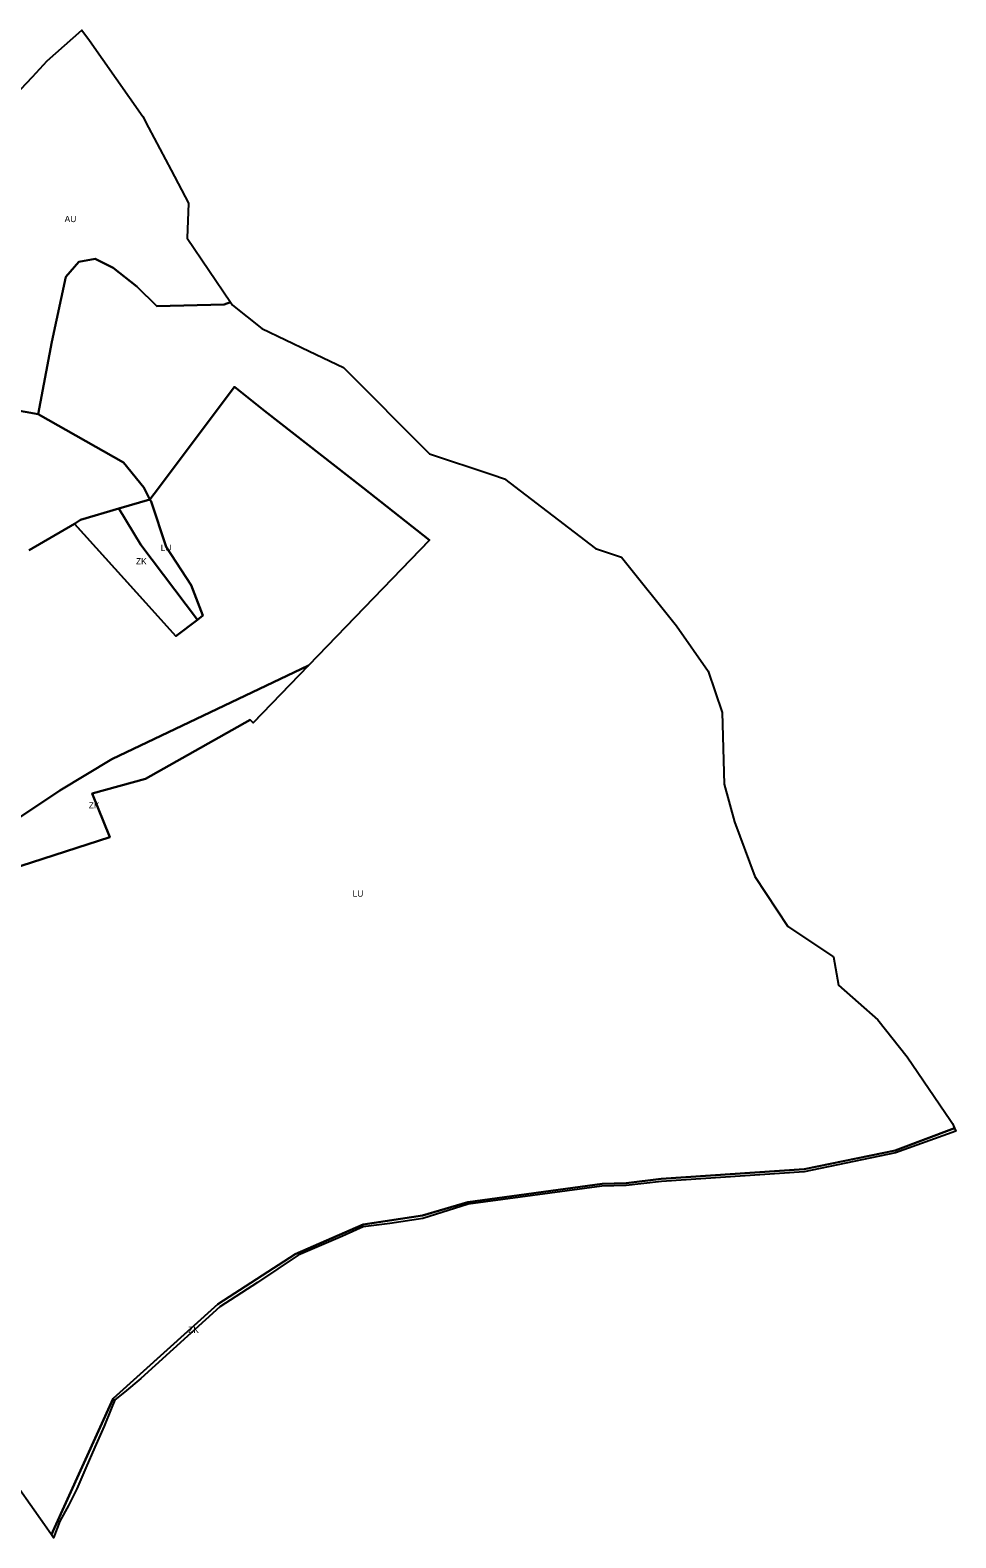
# Model space of a CAD drawing. Extents: x -521261 to -517465, y -1182764 to -1179456.
# Drawn here: x -518203 to -517465, y -1182764 to -1181562 of the extents above; entities that cross this region are included whole.
import ezdxf

# ---------------------------------------------------------------- set-up
doc = ezdxf.new("R2010")
doc.units = 0
for name, color, linetype in [('90710013', 7, 'Continuous'), ('90730013', 7, 'Continuous'), ('90750013', 7, 'Continuous'), ('90770013', 7, 'Continuous')]:
    doc.layers.add(name, color=color, linetype=linetype)

msp = doc.modelspace()

# ---------------------------------------------------------------- linework, layer by layer
at = {"layer": '90710013'}
for points in [[(-518132.326, -1181942.9), (-518114.8, -1181971.88), (-518069.54, -1182031.68), (-518086.87, -1182044.67), (-518110.82, -1182018.11), (-518167.73, -1181955), (-518162.77, -1181951.82)], [(-518263.83, -1182245.02), (-518331.496, -1182282.593), (-518305.68, -1182252.07), (-518179.3, -1182167.62), (-518137.82, -1182142.72), (-517980.99, -1182067.93), (-518025.29, -1182113.9), (-518027.56, -1182111.28), (-518111.08, -1182158.35), (-518153.43, -1182170.1), (-518139.38, -1182204.87)], [(-518186, -1182761.1), (-518185.03, -1182758.6), (-518136.91, -1182652.41), (-518053.48, -1182577.3), (-517991.81, -1182537.48), (-517937.38, -1182513.75), (-517890.3, -1182506.61), (-517854.15, -1182495.98), (-517747.01, -1182481.25), (-517727.83, -1182480.7), (-517699.99, -1182477.2), (-517585.78, -1182469.65), (-517513.36, -1182454.7), (-517465.93, -1182436.99), (-517464.94, -1182439.27), (-517512.98, -1182456.69), (-517585.76, -1182471.75), (-517699.75, -1182479.52), (-517727.75, -1182482.61), (-517747.25, -1182483.11), (-517853.64, -1182497.6), (-517889.93, -1182508.92), (-517916.3, -1182512.99), (-517937.58, -1182515.7), (-517954.01, -1182523.06), (-517989.22, -1182538.07), (-518021.76, -1182560.09), (-518051.88, -1182579.31), (-518114.7, -1182636.54), (-518127.82, -1182647.32), (-518135.52, -1182653.62), (-518138.53, -1182660.75), (-518143.89, -1182674.62), (-518151.47, -1182691.27), (-518158.69, -1182707.68), (-518165.82, -1182724.54), (-518172.44, -1182737.72), (-518179.44, -1182750.16), (-518184.3, -1182763.53)]]:
    msp.add_lwpolyline(points, close=True, dxfattribs=at)
at = {"layer": '90730013'}
msp.add_lwpolyline([(-518217.29, -1181863.99), (-518196.73, -1181867.61), (-518128.46, -1181906.25), (-518112.47, -1181926.13), (-518107.48, -1181935.62), (-518132.326, -1181942.9), (-518162.77, -1181951.82), (-518167.73, -1181955), (-518203.86, -1181976.19)], dxfattribs=at)
at = {"layer": '90750013'}
for points in [[(-518210.43, -1181608.65), (-518201.08, -1181598.66), (-518198.24, -1181595.51), (-518189.41, -1181586), (-518161.68, -1181561.54), (-518155.8, -1181569.88), (-518113.09, -1181630.49), (-518108.52, -1181639.23), (-518090.66, -1181673.2), (-518076.8, -1181699.59), (-518077.8, -1181727.26), (-518043.21, -1181778.53), (-518048.19, -1181780.36), (-518102.12, -1181781.59), (-518117.96, -1181765.95), (-518136.81, -1181751.12), (-518151.04, -1181743.73), (-518164.27, -1181746.2), (-518174.5, -1181758.25), (-518185.6, -1181810.01), (-518196.73, -1181867.61), (-518217.29, -1181863.99)], [(-518203.86, -1181976.19), (-518167.73, -1181955), (-518110.82, -1182018.11), (-518086.87, -1182044.67), (-518069.54, -1182031.68), (-518065.44, -1182028.22), (-518074.66, -1182003.92), (-518094.59, -1181973.57), (-518106.56, -1181937.37), (-518107.48, -1181935.62), (-518104.15, -1181931.16), (-518039.97, -1181846.02), (-518016.25, -1181865.06), (-517937.47, -1181926.51), (-517884.7, -1181968.01), (-517980.99, -1182067.93), (-518137.82, -1182142.72), (-518179.3, -1182167.62), (-518305.68, -1182252.07)]]:
    msp.add_lwpolyline(points, dxfattribs=at)
at = {"layer": '90770013'}
msp.add_lwpolyline([(-518263.83, -1182245.02), (-518139.38, -1182204.87), (-518153.43, -1182170.1), (-518111.08, -1182158.35), (-518027.56, -1182111.28), (-518025.29, -1182113.9), (-517884.7, -1181968.01), (-517937.47, -1181926.51), (-518016.25, -1181865.06), (-518039.97, -1181846.02), (-518104.15, -1181931.16), (-518107.48, -1181935.62), (-518112.47, -1181926.13), (-518128.46, -1181906.25), (-518196.73, -1181867.61), (-518185.6, -1181810.01), (-518174.5, -1181758.25), (-518164.27, -1181746.2), (-518151.04, -1181743.73), (-518136.81, -1181751.12), (-518117.96, -1181765.95), (-518102.12, -1181781.59), (-518048.19, -1181780.36), (-518043.21, -1181778.53), (-518041.71, -1181780.74), (-518018.25, -1181799.32), (-517980.44, -1181817.45), (-517953.14, -1181830.53), (-517884.53, -1181899.44), (-517834.98, -1181915.87), (-517824.86, -1181919.18), (-517752.33, -1181974.82), (-517731.51, -1181981.82), (-517687.7, -1182036.43), (-517662.52, -1182072.49), (-517651.3, -1182105.53), (-517649.72, -1182162.65), (-517641.34, -1182192.65), (-517625.29, -1182236.25), (-517598.88, -1182276.27), (-517562.58, -1182300.26), (-517558.45, -1182323.01), (-517527.07, -1182350.65), (-517503.79, -1182380.06), (-517469.24, -1182430.75), (-517467.55, -1182433.23), (-517465.93, -1182436.99), (-517513.36, -1182454.7), (-517585.78, -1182469.65), (-517699.99, -1182477.2), (-517727.83, -1182480.7), (-517747.01, -1182481.25), (-517854.15, -1182495.98), (-517890.3, -1182506.61), (-517937.38, -1182513.75), (-517991.81, -1182537.48), (-518053.48, -1182577.3), (-518136.91, -1182652.41), (-518185.03, -1182758.6), (-518186, -1182761.1), (-518191.58, -1182753.11), (-518222.72, -1182708.99)], dxfattribs=at)
msp.add_lwpolyline([(-518107.48, -1181935.62), (-518106.56, -1181937.37), (-518094.59, -1181973.57), (-518074.66, -1182003.92), (-518065.44, -1182028.22), (-518069.54, -1182031.68), (-518114.8, -1181971.88), (-518132.326, -1181942.9)], close=True, dxfattribs=at)

# ---------------------------------------------------------------- texts
at = {"layer": '90710013'}
for p in [(-518118.635, -1181987.491), (-518156.243, -1182182.045), (-518076.93, -1182600.26)]:
    msp.add_text('ZK', height=5, rotation=360, dxfattribs=at).set_placement(p)
at = {"layer": '90750013'}
msp.add_text('AU', height=5, rotation=360, dxfattribs=at).set_placement((-518175.503, -1181714.575))
at = {"layer": '90770013'}
msp.add_text('LU', height=5, rotation=360, dxfattribs=at).set_placement((-518098.883, -1181976.749))
msp.add_text('LU', height=5, dxfattribs=at).set_placement((-517945.885, -1182252.415))

doc.saveas('drawing.dxf')
